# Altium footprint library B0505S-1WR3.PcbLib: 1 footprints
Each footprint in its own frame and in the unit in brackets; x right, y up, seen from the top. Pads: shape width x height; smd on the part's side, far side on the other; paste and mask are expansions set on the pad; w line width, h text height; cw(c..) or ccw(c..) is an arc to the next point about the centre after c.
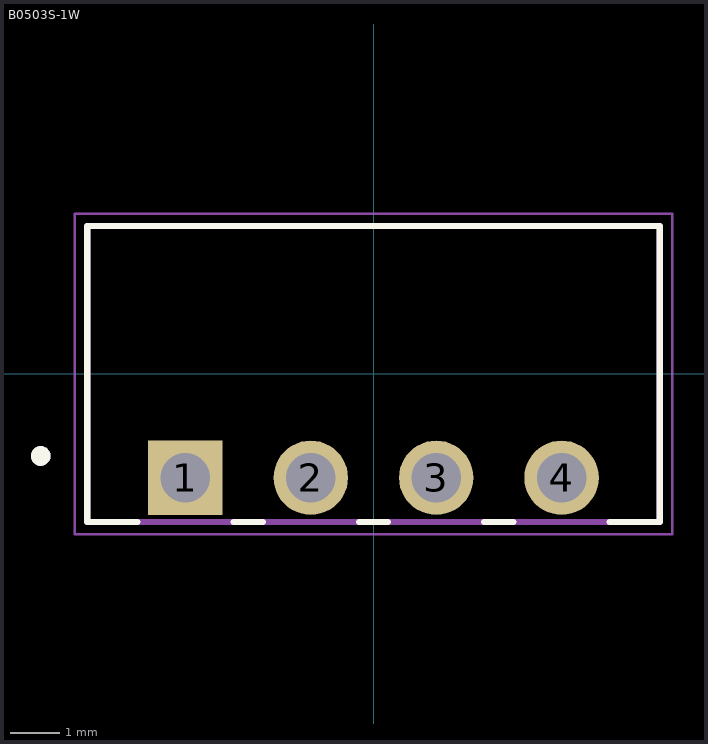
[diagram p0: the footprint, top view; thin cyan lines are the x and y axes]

## B0503S-1W [mm]
pads (4):
  rect 1.508x1.508 hole 1: 1(-3.81,-2.1)
  round 1.508 hole 1: 2(-1.27,-2.1) 3(1.27,-2.1) 4(3.81,-2.1)
Top Overlay:
  circle w0.2: c-6.74,-1.66 r0.1
  lines w0.127: -4.785,-3 -5.8,-3 -5.8,3 5.8,3 5.8,-3 4.785,-3 ; -2.835,-3 -2.245,-3 ; -0.295,-3 0.295,-3 ; 2.245,-3 2.835,-3
Mechanical 13:
  circle w0.2: c-6.74,-1.66 r0.1
  lines w0.127: -5.8,-3 5.8,-3 5.8,3 -5.8,3 -5.8,-3
Mechanical 15:
  lines w0.05: -6.05,-3.25 -6.05,3.25 6.05,3.25 6.05,-3.25 -6.05,-3.25
3D body "B0503S-1W.STEP": height 10.1, standoff -4.1, extent -5.8,-3.048 5.8,2.952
